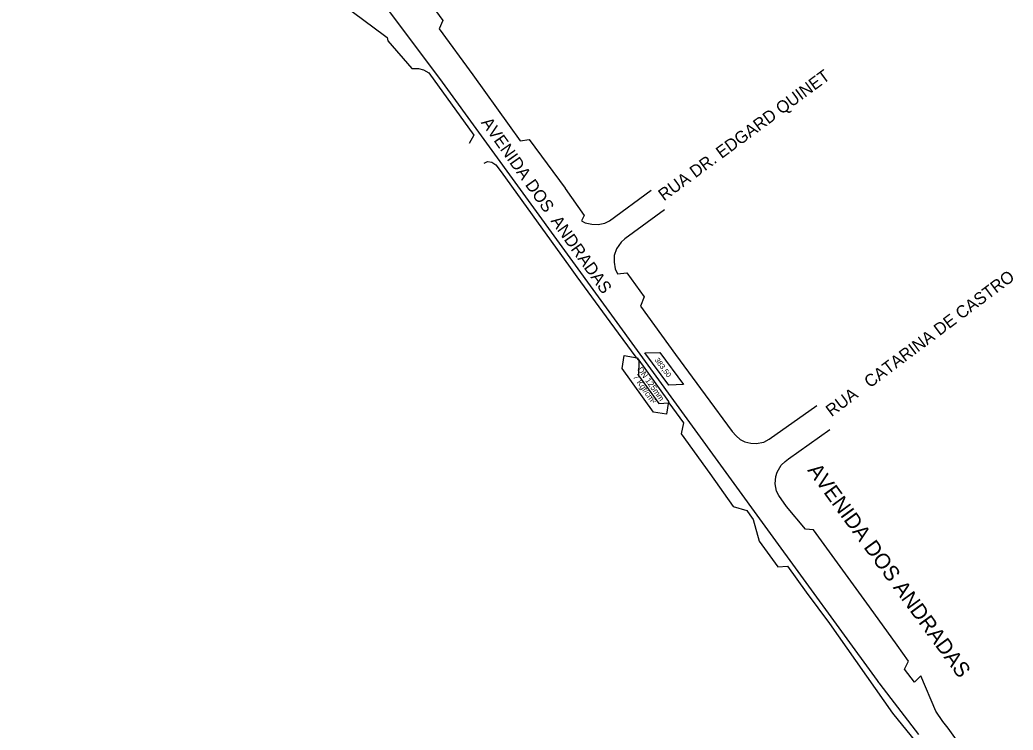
# Model space of a CAD drawing. Extents: x 656692 to 673945, y 7585994 to 7599066.
# Drawn here: x 668888 to 669475, y 7596147 to 7596567 of the extents above; entities that cross this region are included whole.
import ezdxf

# ---------------------------------------------------------------- set-up
doc = ezdxf.new("R2010")
doc.units = 0
for name, color, linetype in [('LOGRADOURO', 7, 'Continuous'), ('LOGRADOURO_TEXTO', 7, 'Continuous'), ('SIMBOLO', 7, 'Continuous'), ('TEXTO', 7, 'Continuous'), ('TUBO_PEAD_GN_125', 7, 'Continuous')]:
    doc.layers.add(name, color=color, linetype=linetype)

msp = doc.modelspace()

# ---------------------------------------------------------------- linework, layer by layer
at = {"layer": 'LOGRADOURO'}
for points in [[(668888.39, 7596760.83), (668904.79, 7596759.76), (668919.5, 7596757.92), (668928.98, 7596755.35), (668942.47, 7596750.41), (668953.79, 7596743.03), (668955.78, 7596740.56), (668959.86, 7596731.87), (668975.11, 7596694.68), (669047.1, 7596598.97), (669061.66, 7596588.26), (669079.15, 7596575.6), (669103.66, 7596557.52), (669105.1, 7596556.26), (669105.64, 7596554.27), (669119.79, 7596537.87), (669123.71, 7596537.97), (669126.65, 7596537.21), (669129.8, 7596535.38), (669156.26, 7596498.62), (669153.65, 7596493.64)], [(669130.87, 7596576), (669138, 7596566.28), (669135.85, 7596561.31), (669155.8, 7596534.19), (669177.23, 7596504.26), (669183.69, 7596495.24), (669189.05, 7596496.05), (669210.24, 7596467.26), (669210.28, 7596467.18), (669221.46, 7596451.23), (669219.92, 7596447.96), (669222.06, 7596446.78), (669226, 7596446.01), (669229.75, 7596445.77), (669233.58, 7596446.69), (669236.46, 7596448.08), (669261.05, 7596466.08)], [(669162.33, 7596482.07), (669164.39, 7596482.96), (669166.92, 7596482.69), (669169.25, 7596481.06), (669172.37, 7596476.87), (669190.71, 7596451.49), (669213.11, 7596420.47), (669217.14, 7596415.03), (669236.61, 7596388.44), (669252, 7596367.54), (669253.8, 7596365.52), (669253.6, 7596356.66), (669265.55, 7596340.15), (669271.38, 7596340.47), (669280, 7596328.65), (669278.6, 7596322.19), (669295.53, 7596298.85), (669309.33, 7596279.32), (669317.48, 7596276.91), (669319.26, 7596274.42), (669321.11, 7596271.59), (669324.72, 7596258.84), (669324.76, 7596258.82), (669335.71, 7596243.77), (669341.43, 7596244.04), (669352.42, 7596228.82), (669366.26, 7596210.17), (669403.4, 7596157.23), (669416.98, 7596140.49)], [(669268.88, 7596454.4), (669245.36, 7596437.3), (669243.22, 7596435.33), (669240.58, 7596431.4), (669239.15, 7596427.46), (669239.06, 7596423.67), (669239.68, 7596419.67), (669241.16, 7596416.77), (669246.67, 7596417.32), (669256.76, 7596403.19), (669254.71, 7596397.68), (669275.42, 7596369), (669292.85, 7596345.33), (669308.83, 7596323.65), (669311.1, 7596321.11), (669313.51, 7596318.88), (669316.24, 7596317.53), (669319.74, 7596316.73), (669323.04, 7596316.61), (669327.42, 7596317.29), (669330.54, 7596319.07), (669358.73, 7596338.95)], [(669447.71, 7596132.4), (669436.32, 7596148.42), (669433.17, 7596152.4), (669429.02, 7596158.45), (669420.11, 7596179.36), (669416.37, 7596175.59), (669410.53, 7596183.25), (669412.9, 7596188.08), (669406.24, 7596197.52), (669389.91, 7596220.08), (669356.73, 7596265.48), (669352.17, 7596266.01), (669352.07, 7596265.89), (669340.83, 7596279.31), (669336.38, 7596285.73), (669335.03, 7596288.47), (669334.18, 7596292.7), (669334.57, 7596296.96), (669335.34, 7596299.51), (669337.78, 7596303.81), (669340.04, 7596305.96), (669342.01, 7596307.46), (669366.46, 7596324.78)]]:
    msp.add_lwpolyline(points, dxfattribs=at)
at = {"layer": 'SIMBOLO'}
msp.add_lwpolyline([(669245.15, 7596368.4), (669252.8, 7596367.13), (669271.22, 7596341.4), (669269.95, 7596333.75), (669262.3, 7596335.02), (669243.89, 7596360.75), (669245.15, 7596368.4)], dxfattribs=at)
at = {"layer": 'TEXTO'}
msp.add_lwpolyline([(669266.09, 7596370.26), (669280.07, 7596351.37), (669271.32, 7596351.04), (669257.25, 7596370.05), (669266.09, 7596370.26)], dxfattribs=at)
at = {"layer": 'TUBO_PEAD_GN_125'}
msp.add_line((669395.93, 7596174.39), (669418.86, 7596144.6), dxfattribs=at)
msp.add_lwpolyline([(668913.63, 7596803.66), (668984.43, 7596737.17), (668997.63, 7596721.25), (669012.41, 7596703.43), (669045.9, 7596655.71), (669082.31, 7596603.85), (669137.54, 7596529.8), (669329.63, 7596265.54), (669394.29, 7596176.59)], dxfattribs=at)
msp.add_arc((669475.27, 7596235.45), 100.12, 216.01298, 217.58241, dxfattribs=at)

# ---------------------------------------------------------------- texts
at = {"layer": 'LOGRADOURO_TEXTO'}
for s, rotation, p in [('RUA DR. EDGARD QUINET', 36.35798, (669268.53, 7596459.42)), ('AVENIDA DOS  ANDRADAS', 305.31555, (669160.34, 7596505.97)), ('RUA   CATARINA DE CASTRO', 36.89452, (669367.44, 7596332.01))]:
    msp.add_text(s, height=7.2, rotation=rotation, dxfattribs=at).set_placement(p)
at = {"layer": 'TEXTO'}
for s, height, rotation, p in [('383,50', 3.113, 306.50717, (669262.87, 7596365.79)), ('DN 125mm', 3.459, 305.59078, (669252.68, 7596360.19)), ('7 Kgf/cm²', 3.459, 305.59078, (669249.99, 7596355.71)), ('AVENIDA DOS ANDRADAS', 9.011, 306.10636, (669352.92, 7596300.7))]:
    msp.add_text(s, height=height, rotation=rotation, dxfattribs=at).set_placement(p)

doc.saveas('drawing.dxf')
